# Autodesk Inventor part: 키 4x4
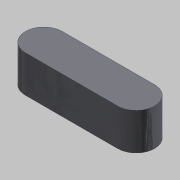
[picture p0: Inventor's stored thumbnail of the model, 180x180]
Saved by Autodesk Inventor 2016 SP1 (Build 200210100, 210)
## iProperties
Created: 2016-04
Part Number: 키 4x4
Document SubType Name: Modeling
Designer: mdu
Density: 7.86 g/cm^3
Mass: 1.65269 g
Surface Area: 2.35398 cm^2
Volume: 0.210265 cm^3
Material: 강철, 연강
Appearance: 강철 - 광택
Author: mdu
Revision Number: 1
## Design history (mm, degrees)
sketch "스케치1"
  geometry: L1 (-5, -2)-(5, -2); L2 (5, 2)-(-5, 2); A1 r 2 centre (5, 0) between (5, -2) and (5, 2); A2 r 2 centre (-5, 0) between (-5, 2) and (-5, -2); 2 further points
  constraints: 4 end point, 4 point on circle, 4 tangent, 2 centre point, 1 horizontal, 1 horizontal alignment, 1 midpoint, 1 parallel, 1 vertical alignment
  dimensions: "d0" = 4 distance between parallel lines of L1 L2; "d1" = 14 dimension on A1 A2
extrude "돌출1" new body sketch "스케치1" stored distance "d2" = 4; taper "d3" = 0 deg
node "솔리드1"
